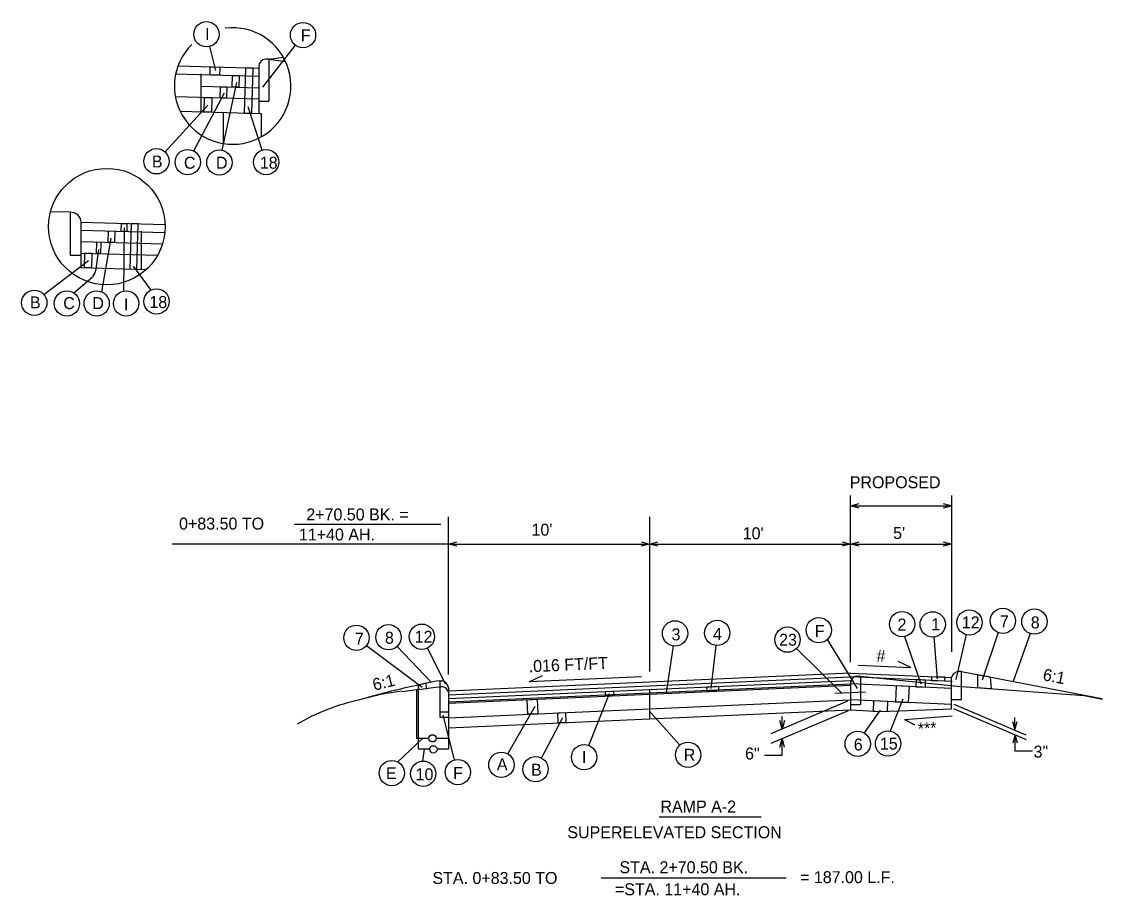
# Model space of a CAD drawing. Extents: x -210 to 558, y -150 to 205.
# Drawn here: x 371.3 to 425.5, y -4.9 to 38.9 of the extents above; entities that cross this region are included whole.
import ezdxf

# ---------------------------------------------------------------- set-up
doc = ezdxf.new("R2010")
doc.units = 0
for name, color, linetype in [('Level 4', 7, 'Continuous'), ('Level 6', 7, 'Continuous'), ('Level 60', 7, 'Continuous'), ('Level 7', 7, 'Continuous')]:
    doc.layers.add(name, color=color, linetype=linetype)

msp = doc.modelspace()

# ---------------------------------------------------------------- linework, layer by layer
at = {"layer": 'Level 4'}
for p, q in [((380.756, 37.681), (381.06, 36.474)), ((385.053, 37.754), (383.419, 35.64)), ((381.385, 32.49), (382.118, 35.884)), ((379.963, 32.45), (381.508, 35.355)), ((378.527, 32.399), (380.674, 34.745)), ((383.398, 32.493), (382.687, 34.664)), ((376.479, 28.609), (376.449, 25.427)), ((375.358, 25.386), (375.83, 28.085)), ((375.191, 27.517), (375.049, 26.424)), ((372.456, 25.256), (374.685, 26.957)), ((376.923, 26.673), (377.823, 25.476)), ((373.95, 25.341), (374.854, 26.114)), ((412.881, 6.832), (412.881, 15.183)), ((417.942, 7.347), (417.942, 15.183)), ((412.881, 14.665), (417.942, 14.665)), ((392.724, 6.206), (392.724, 14.107)), ((402.802, 14.107), (402.802, 6.357)), ((385.017, 13.737), (392.348, 13.737)), ((392.724, 12.75), (378.878, 12.75)), ((392.724, 12.75), (402.802, 12.75)), ((402.802, 12.75), (412.881, 12.75)), ((412.881, 12.75), (417.942, 12.75)), ((417.942, 7.347), (417.942, 10.934)), ((418.66, 8.207), (418.145, 5.962)), ((420.265, 8.314), (419.476, 5.924)), ((421.875, 8.267), (421.023, 5.866)), ((388.623, 7.672), (391.416, 5.58)), ((390.16, 7.618), (391.86, 5.828)), ((403.99, 7.643), (403.644, 5.287)), ((406.124, 7.664), (405.877, 5.501)), ((411.712, 7.964), (413.208, 5.513)), ((415.573, 8.11), (416.393, 5.744)), ((417.042, 8.09), (417.211, 5.995)), ((391.678, 7.536), (392.566, 5.737)), ((412.421, 5.286), (410.168, 7.511)), ((413.262, 6.684), (415.895, 6.566)), ((415.895, 6.566), (415.263, 6.87)), ((396.77, 5.841), (397.435, 6.161)), ((402.396, 6.094), (396.77, 5.841)), ((399.761, 2.654), (400.802, 5.253)), ((412.723, 4.875), (408.888, 3.243)), ((415.5, 4.967), (414.863, 3.372)), ((395.698, 2.235), (397.076, 4.626)), ((404.315, 2.662), (402.802, 4.379)), ((412.755, 4.391), (408.888, 2.746)), ((414.351, 4.424), (413.559, 3.279)), ((418.026, 4.5), (421.671, 2.949)), ((418.057, 4.728), (421.661, 3.195)), ((393.039, 1.934), (392.461, 4.168)), ((397.389, 2.025), (398.462, 4.064)), ((409.442, 3.479), (409.442, 4.108)), ((415.574, 3.96), (417.967, 4.131)), ((415.574, 3.96), (416.088, 3.696)), ((421.107, 3.431), (421.107, 4.06)), ((391.445, 3.012), (390.191, 1.829)), ((409.442, 2.167), (409.442, 2.982)), ((421.117, 2.37), (421.117, 3.185)), ((391.505, 2.485), (391.431, 1.874)), ((408.566, 2.167), (409.442, 2.167)), ((421.993, 2.37), (421.117, 2.37)), ((403.291, -0.915), (408.399, -0.915)), ((400.374, -3.987), (409.644, -3.987))]:
    msp.add_line(p, q, dxfattribs=at)
for points in [[(413.301, 14.549), (412.881, 14.665), (413.301, 14.777)], [(417.522, 14.781), (417.942, 14.665), (417.522, 14.553)], [(393.144, 12.634), (392.724, 12.75), (393.144, 12.862)], [(402.382, 12.866), (402.802, 12.75), (402.382, 12.638)], [(403.222, 12.634), (402.802, 12.75), (403.222, 12.862)], [(412.461, 12.866), (412.881, 12.75), (412.461, 12.638)], [(413.301, 12.634), (412.881, 12.75), (413.301, 12.862)], [(417.522, 12.866), (417.942, 12.75), (417.522, 12.638)], [(409.558, 3.899), (409.442, 3.479), (409.33, 3.899)], [(420.991, 3.851), (421.107, 3.431), (421.219, 3.851)], [(409.326, 2.562), (409.442, 2.982), (409.554, 2.562)], [(421.233, 2.765), (421.117, 3.185), (421.005, 2.765)]]:
    msp.add_lwpolyline(points, dxfattribs=at)
for centre in [(380.601, 38.296), (385.441, 38.255), (378.099, 31.931), (379.665, 31.89), (381.251, 31.87), (383.595, 31.89), (371.976, 24.841), (378.101, 24.906), (373.61, 24.806), (375.102, 24.806), (376.576, 24.806), (415.459, 8.734), (416.991, 8.722), (418.832, 8.817), (420.507, 8.9), (422.086, 8.864), (388.116, 8.052), (389.724, 8.078), (391.397, 8.104), (404.082, 8.271), (406.196, 8.294), (411.283, 8.431), (409.718, 7.958), (413.233, 2.736), (414.753, 2.748), (404.734, 2.186), (395.381, 1.686), (399.525, 2.065), (389.889, 1.271), (391.464, 1.24), (393.198, 1.32), (397.093, 1.464)]:
    msp.add_circle(centre, 0.634, dxfattribs=at)
msp.add_arc((374.565, 26.512), 0.491, 305.9071, 349.765, dxfattribs=at)
at = {"layer": 'Level 6'}
for p, q in [((383.727, 37.051), (383.575, 37.051)), ((383.727, 37.051), (384.457, 37.15)), ((383.727, 37.051), (383.727, 34.936)), ((383.727, 37.051), (384.556, 36.933)), ((379.035, 36.315), (383.227, 36.199)), ((379.178, 36.707), (383.227, 36.596)), ((380.338, 34.407), (380.338, 36.308)), ((383.227, 36.677), (383.227, 34.327)), ((380.338, 35.693), (383.227, 35.613)), ((379.043, 35.171), (383.227, 35.056)), ((383.227, 34.936), (383.727, 34.936)), ((379.292, 34.435), (383.346, 34.324)), ((381.435, 34.376), (381.435, 32.822)), ((383.346, 34.324), (383.346, 33.156)), ((373.773, 29.375), (372.789, 29.405)), ((373.773, 29.375), (373.773, 27.226)), ((374.306, 28.896), (374.306, 26.605)), ((374.306, 28.874), (378.532, 28.758)), ((374.306, 28.477), (378.519, 28.361)), ((377.338, 28.422), (377.338, 26.522)), ((374.342, 27.911), (378.406, 27.799)), ((373.773, 27.226), (374.306, 27.226)), ((374.306, 27.334), (378.162, 27.228)), ((374.306, 26.605), (377.6, 26.515)), ((413.155, 6.128), (413.381, 6.128)), ((413.381, 6.128), (418.215, 5.619)), ((413.381, 6.128), (413.381, 4.712)), ((391.129, 5.454), (391.129, 3.012)), ((392.301, 5.601), (392.301, 4.075)), ((392.301, 5.601), (392.455, 5.601)), ((392.724, 5.012), (412.881, 5.917)), ((392.724, 4.771), (412.881, 5.676)), ((402.802, 5.464), (402.802, 3.992)), ((412.881, 5.917), (412.881, 4.445)), ((418.215, 5.619), (424.575, 5.156)), ((392.724, 5.308), (392.724, 3.012)), ((392.724, 4.037), (412.881, 4.942)), ((424.575, 5.156), (425.493, 4.982)), ((392.724, 3.54), (412.881, 4.445)), ((412.881, 4.712), (413.381, 4.712)), ((392.301, 4.075), (392.724, 4.075)), ((391.129, 3.012), (391.719, 3.012)), ((392.11, 3.012), (392.724, 3.012))]:
    msp.add_line(p, q, dxfattribs=at)
msp.add_circle((391.929, 3.011), 0.183, dxfattribs=at)
for centre, radius, start, end in [((383.59, 36.689), 0.363, 92.2758, 181.8476), ((373.806, 28.863), 0.513, 1.1262, 93.6963), ((413.242, 5.776), 0.363, 103.893, 186.0164), ((304.027, 709.15), 709.066, 276.998467, 277.151492), ((392.37, 5.252), 0.359, 8.9116, 76.2466), ((390.578, -5.584), 10.774, 102.2857, 120.3111), ((391.701, -6.66), 12.095, 96.0719, 106.453)]:
    msp.add_arc(centre, radius, start, end, dxfattribs=at)
at = {"layer": 'Level 60'}
for points in [[(380.784, 36.266), (380.795, 36.663), (381.274, 36.65), (381.263, 36.253)], [(382.552, 36.614), (382.49, 34.347), (382.883, 34.337), (382.946, 36.604)], [(381.898, 35.65), (381.914, 36.235), (382.249, 36.226), (382.233, 35.641)], [(381.291, 35.109), (381.306, 35.666), (381.626, 35.657), (381.61, 35.1)], [(380.491, 34.402), (380.511, 35.131), (380.871, 35.121), (380.851, 34.393)], [(376.332, 28.422), (376.343, 28.818), (376.616, 28.81), (376.606, 28.414)], [(376.83, 28.804), (376.767, 26.538), (377.123, 26.528), (377.185, 28.795)], [(375.675, 27.874), (375.691, 28.439), (376.013, 28.43), (375.998, 27.866)], [(375.088, 27.312), (375.104, 27.89), (375.311, 27.884), (375.295, 27.307)], [(374.493, 26.6), (374.513, 27.328), (374.859, 27.319), (374.839, 26.59)], [(417.601, 5.885), (417.609, 6.071), (416.936, 6.102), (416.928, 5.916)], [(419.253, 5.543), (419.245, 6.212), (419.871, 6.09), (419.918, 5.495)], [(391.22, 5.466), (391.625, 5.516), (391.618, 5.769), (391.203, 5.676)], [(405.687, 5.353), (405.676, 5.593), (406.256, 5.619), (406.267, 5.379)], [(415.785, 4.812), (415.821, 5.607), (415.168, 5.637), (415.132, 4.841)], [(416.623, 5.576), (416.639, 5.93), (416.16, 5.952), (416.144, 5.598)], [(396.71, 4.216), (396.677, 4.949), (397.173, 4.971), (397.206, 4.238)], [(400.605, 5.125), (400.594, 5.365), (400.997, 5.383), (401.007, 5.143)], [(414.014, 4.381), (414.408, 4.363), (414.72, 4.374), (414.751, 4.853), (414.028, 4.883)], [(398.232, 3.787), (398.209, 4.283), (398.587, 4.3), (398.61, 3.804)]]:
    msp.add_lwpolyline(points, close=True, dxfattribs=at)
at = {"layer": 'Level 7'}
for p, q in [((412.879, 6.281), (392.724, 5.376)), ((392.724, 5.189), (412.879, 6.094)), ((412.879, 6.281), (417.94, 6.053)), ((417.963, 5.866), (412.879, 6.094)), ((417.94, 4.49), (417.94, 6.053)), ((418.44, 6.369), (418.28, 6.369)), ((418.44, 6.369), (425.458, 5.002)), ((418.44, 4.963), (418.44, 6.369)), ((391.219, 5.68), (391.219, 2.485)), ((392.301, 5.901), (392.301, 4.346)), ((392.301, 5.901), (392.392, 5.901)), ((392.724, 4.835), (412.894, 5.74)), ((392.724, 5.538), (392.724, 2.485)), ((412.879, 5.74), (412.879, 4.435)), ((417.927, 5.513), (412.879, 5.74)), ((412.091, 5.273), (413.632, 5.335)), ((417.94, 4.715), (412.879, 4.942)), ((417.94, 4.963), (418.44, 4.963)), ((392.301, 4.346), (392.724, 4.346)), ((412.879, 4.435), (414.408, 4.363)), ((414.408, 4.363), (417.94, 4.49)), ((391.219, 2.485), (391.794, 2.485)), ((392.155, 2.485), (392.724, 2.485))]:
    msp.add_line(p, q, dxfattribs=at)
for centre, radius in [((375.614, 28.655), 2.92), ((391.974, 2.459), 0.183)]:
    msp.add_circle(centre, radius, dxfattribs=at)
for centre, radius, start, end in [((381.916, 35.702), 2.92, 134.4667, 97.2999), ((418.321, 5.984), 0.387, 96.0275, 169.6786), ((396.859, -23.339), 29.551, 101.4847, 106.5755), ((395.464, -12.326), 18.499, 99.8448, 104.0425), ((392.325, 5.506), 0.4, 4.5012, 80.3635)]:
    msp.add_arc(centre, radius, start, end, dxfattribs=at)

# ---------------------------------------------------------------- texts
at = {"layer": 'Level 4'}
for s, p in [('I', (380.532, 38.004)), ('F', (385.331, 37.943)), ('B', (377.868, 31.619)), ('C', (379.474, 31.558)), ('D', (381.081, 31.558)), ('18', (383.277, 31.558)), ('B', (371.759, 24.557)), ('C', (373.428, 24.522)), ('D', (374.885, 24.522)), ('I', (376.465, 24.468)), ('18', (377.744, 24.575)), ('PROPOSED', (412.836, 15.545)), ('0+83.50 TO', (379.231, 13.474)), ('2+70.50 BK. =', (385.606, 13.932)), ("10'", (396.89, 13.168)), ("10'", (407.473, 12.988)), ("5'", (415.009, 13.002)), ('11+40 AH.', (385.236, 12.927)), ('F', (411.085, 8.093)), ('2', (415.23, 8.413)), ('1', (416.917, 8.425)), ('12', (418.449, 8.52)), ('7', (420.361, 8.58)), ('8', (421.905, 8.52)), ('7', (388.043, 7.711)), ('8', (389.546, 7.751)), ('12', (391.036, 7.803)), ('3', (403.906, 7.92)), ('4', (405.984, 7.944)), ('23', (409.296, 7.652)), ('#', (414.175, 6.839)), ('6', (413.039, 2.404)), ('15', (414.346, 2.451)), ('I', (399.416, 1.777)), ('R', (404.518, 1.886)), ('6"', (407.59, 1.95)), ('3"', (422.046, 2.045)), ('A', (395.154, 1.41)), ('B', (396.867, 1.136)), ('E', (389.595, 0.966)), ('10', (391.082, 0.909)), ('F', (392.962, 0.977)), ('RAMP A-2', (403.35, -0.707)), ('SUPERELEVATED SECTION', (398.685, -1.995)), ('STA. 2+70.50 BK. ', (401.296, -3.747)), ('STA. 0+83.50 TO', (391.924, -4.287)), ('= 187.00 L.F.', (410.346, -4.246)), ('=STA. 11+40 AH.', (401.071, -4.851))]:
    msp.add_text(s, height=0.6, dxfattribs=at).set_placement(p)
for s, rotation, p in [('.016 FT/FT', 2.5707, (396.762, 6.319)), ('6:1', 348.9796, (422.474, 5.931)), ('6:1', 13.9187, (389.01, 5.393)), ('***', 4.0774, (416.274, 3.187))]:
    msp.add_text(s, height=0.6, rotation=rotation, dxfattribs=at).set_placement(p)

doc.saveas('drawing.dxf')
